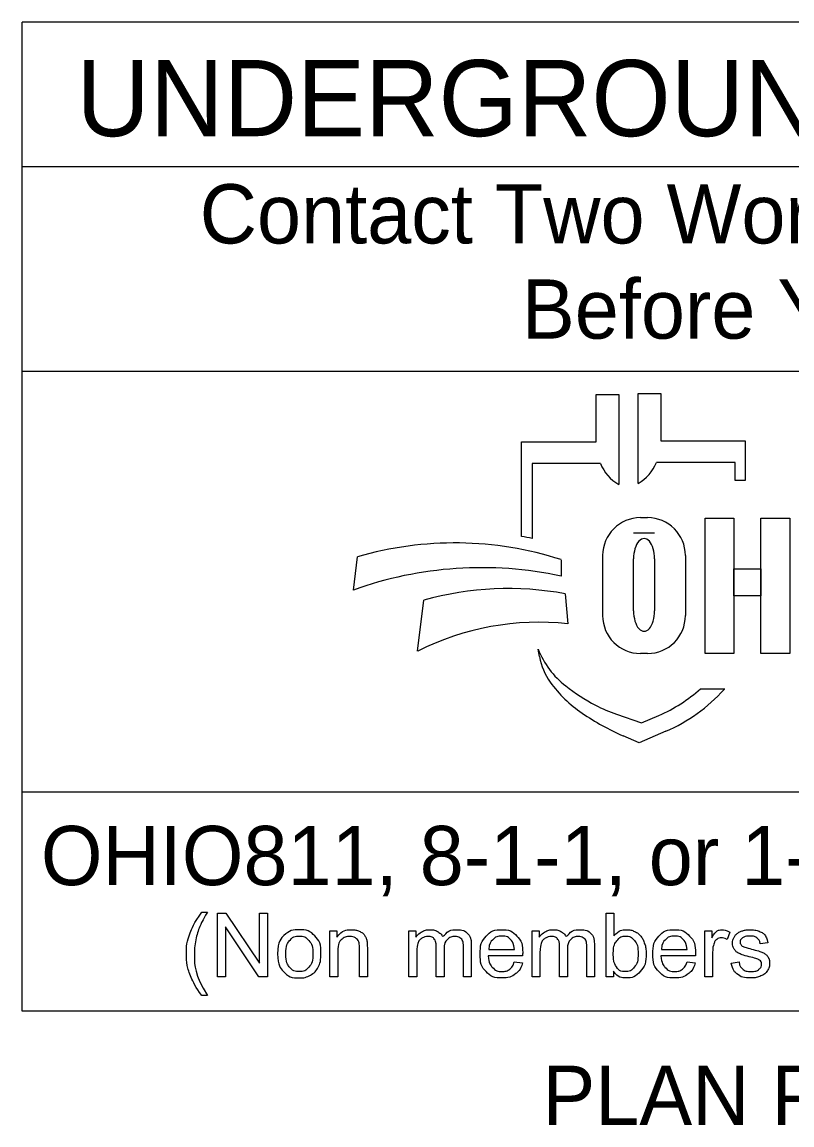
# Model space of a CAD drawing. Extents: x 0 to 34, y 0 to 22.
# Drawn here: x 2.383 to 4.202, y 2.813 to 5.419 of the extents above; entities that cross this region are included whole.
import ezdxf

# ---------------------------------------------------------------- set-up
doc = ezdxf.new("R2010")
doc.units = 0
doc.layers.add('SH_Data', color=7, linetype='Continuous')
doc.layers.add('SH_Text', color=7, linetype='Continuous')

msp = doc.modelspace()

# ---------------------------------------------------------------- linework, layer by layer
at = {"layer": 'SH_Data'}
for p, q in [((2.3833, 3.0815), (2.3833, 5.419)), ((6.6333, 5.419), (2.3833, 5.419)), ((2.3833, 5.0774), (6.6333, 5.0774)), ((2.3833, 4.594), (6.6333, 4.594)), ((6.6333, 3.5994), (2.3833, 3.5994)), ((6.6333, 3.0815), (2.3833, 3.0815))]:
    msp.add_line(p, q, dxfattribs=at)
at = {"layer": 'SH_Text'}
for p, q in [((3.7393, 4.427), (3.7393, 4.5385)), ((3.7393, 4.5385), (3.793, 4.5385)), ((3.793, 4.5385), (3.793, 4.3264)), ((3.8387, 4.3287), (3.8387, 4.5408)), ((3.8387, 4.5408), (3.8923, 4.5408)), ((3.8923, 4.5408), (3.8923, 4.4293)), ((3.5634, 4.2031), (3.5634, 4.427)), ((3.5634, 4.427), (3.7393, 4.427)), ((3.8923, 4.4293), (4.0915, 4.4293)), ((4.0915, 4.4293), (4.0915, 4.3355)), ((3.5886, 4.3755), (3.5886, 4.1987)), ((3.7497, 4.3755), (3.5886, 4.3755)), ((4.0682, 4.3779), (3.8819, 4.3779)), ((4.0682, 4.3355), (4.0682, 4.3779)), ((4.0915, 4.3355), (4.0682, 4.3355)), ((3.8443, 4.2478), (3.8609, 4.2478)), ((3.8776, 4.2108), (3.8278, 4.2108)), ((3.166, 4.0768), (3.1754, 4.1549)), ((3.6567, 4.1484), (3.6567, 4.1096)), ((3.7549, 4.0163), (3.7549, 4.1583)), ((3.8278, 4.0277), (3.8278, 4.1501)), ((3.8776, 4.1501), (3.8776, 4.0277)), ((3.9503, 4.1583), (3.9503, 4.0163)), ((3.6666, 4.0678), (3.6729, 3.9969)), ((3.3178, 3.9323), (3.3325, 4.0524)), ((3.6055, 3.9194), (3.6025, 3.9373)), ((3.8609, 3.9269), (3.8443, 3.9269)), ((3.9858, 3.8435), (4.0432, 3.8435)), ((3.7874, 3.7831), (3.8468, 3.7626)), ((3.8468, 3.7626), (3.8879, 3.7804)), ((3.8408, 3.7156), (3.8034, 3.7321)), ((3.9041, 3.7431), (3.8408, 3.7156))]:
    msp.add_line(p, q, dxfattribs=at)
for points in [[(3.9968, 4.2468), (4.0647, 4.2468), (4.0647, 3.9268), (3.9968, 3.9268)], [(4.1289, 4.2468), (4.1969, 4.2468), (4.1969, 3.9268), (4.1289, 3.9268)], [(4.0647, 4.1269), (4.1289, 4.1269), (4.1289, 4.0629), (4.0647, 4.0629)]]:
    msp.add_lwpolyline(points, close=True, dxfattribs=at)
for points in [[(2.8079, 3.3153), (2.8211, 3.3153)], [(2.8447, 3.1626), (2.8447, 3.3128), (2.865, 3.3128), (2.944, 3.1948), (2.944, 3.3128), (2.963, 3.3128), (2.963, 3.1626), (2.9427, 3.1626), (2.8637, 3.2806), (2.8637, 3.1626), (2.8447, 3.1626)], [(3.7801, 3.1626), (3.7631, 3.1626), (3.7631, 3.3128), (3.7815, 3.3128), (3.7815, 3.2593)], [(3.1106, 3.1626), (3.1106, 3.2715), (3.1272, 3.2715), (3.1272, 3.256)], [(3.297, 3.1626), (3.297, 3.2715), (3.3135, 3.2715), (3.3135, 3.2561)], [(3.5884, 3.1626), (3.5884, 3.2715), (3.6049, 3.2715), (3.6049, 3.2561)], [(3.9962, 3.1626), (3.9962, 3.2715), (4.0128, 3.2715), (4.0128, 3.255)], [(4.0553, 3.268), (4.0488, 3.2509)], [(3.3801, 3.2258), (3.3801, 3.1626), (3.3617, 3.1626), (3.3617, 3.2333)], [(3.4446, 3.2373), (3.4446, 3.1626), (3.4261, 3.1626), (3.4261, 3.2311)], [(3.6715, 3.2258), (3.6715, 3.1626), (3.6531, 3.1626), (3.6531, 3.2333)], [(3.7359, 3.2373), (3.7359, 3.1626), (3.7175, 3.1626), (3.7175, 3.2311)], [(4.1452, 3.2433), (4.1271, 3.2409)], [(3.1291, 3.222), (3.1291, 3.1626), (3.1106, 3.1626)], [(3.199, 3.2295), (3.199, 3.1626), (3.1806, 3.1626), (3.1806, 3.2288)], [(3.3155, 3.219), (3.3155, 3.1626), (3.297, 3.1626)], [(3.5658, 3.2123), (3.4846, 3.2123)], [(3.4857, 3.2274), (3.5464, 3.2274)], [(3.6068, 3.219), (3.6068, 3.1626), (3.5884, 3.1626)], [(3.9738, 3.2123), (3.8926, 3.2123)], [(3.8937, 3.2274), (3.9544, 3.2274)], [(4.0146, 3.2196), (4.0146, 3.1626), (3.9962, 3.1626)], [(3.5462, 3.1978), (3.5653, 3.1954)], [(3.9542, 3.1978), (3.9733, 3.1954)], [(4.0588, 3.1951), (4.077, 3.198)], [(3.7801, 3.1762), (3.7801, 3.1626)], [(2.8211, 3.1184), (2.8079, 3.1184)]]:
    msp.add_lwpolyline(points, dxfattribs=at)
for centre, radius, start, end in [((3.8411, 4.4123), 0.0985, 201.9296, 240.7469), ((3.7905, 4.4146), 0.0985, 299.2531, 338.0704), ((3.8443, 4.1583), 0.0895, 90, 180), ((3.8609, 4.1583), 0.0895, 0, 90), ((3.4353, 3.3941), 0.8191, 79.2074, 81.0007), ((3.4055, 3.3689), 0.8191, 72.1402, 106.3144), ((3.4686, 3.2377), 0.8919, 77.8238, 109.8274), ((3.5325, 3.3481), 0.7322, 79.44, 105.8467), ((3.8443, 4.0163), 0.0895, 180, 270), ((3.8609, 4.0163), 0.0895, 270, 0), ((3.6045, 3.3649), 0.6357, 83.8248, 116.8021), ((3.7899, 4.0094), 0.2008, 201.0457, 232.5314), ((3.7468, 3.9435), 0.1433, 189.6817, 216.0884), ((3.8805, 4.0409), 0.3088, 216.0884, 235.7167), ((3.9824, 4.2606), 0.5173, 232.5314, 241.794), ((3.7445, 4.1109), 0.3602, 293.4582, 312.0712), ((3.7445, 4.1109), 0.401, 293.4582, 317.8286), ((4.047, 4.2852), 0.6044, 235.7167, 246.2325), ((3.8972, 4.1018), 0.3371, 241.794, 250.9821)]:
    msp.add_arc(centre, radius, start, end, dxfattribs=at)
for centre, start_param, end_param in [((3.8527, 4.1501), 4.712389, 7.853982), ((3.8527, 4.0277), 1.570796, 4.712389)]:
    msp.add_ellipse(centre, major_axis=(0, 0.0484), ratio=0.514403, start_param=start_param, end_param=end_param, dxfattribs=at)
for points in [[(2.8079, 3.1184), (2.7927, 3.1377), (2.7821, 3.1635), (2.7715, 3.1893), (2.7715, 3.217), (2.7715, 3.2413), (2.7794, 3.2637), (2.7887, 3.2896), (2.8079, 3.3153)], [(2.8211, 3.3153), (2.8087, 3.294), (2.8047, 3.2849), (2.7985, 3.2707), (2.7949, 3.2554), (2.7905, 3.2362), (2.7905, 3.2169), (2.7905, 3.1676), (2.8211, 3.1184)], [(2.9871, 3.217), (2.9871, 3.2472), (3.0039, 3.2618), (3.018, 3.2739), (3.0381, 3.2739), (3.0605, 3.2739), (3.0748, 3.2592), (3.089, 3.2445), (3.089, 3.2186), (3.089, 3.1976), (3.0827, 3.1856), (3.0764, 3.1735), (3.0644, 3.1669), (3.0524, 3.1602), (3.0381, 3.1602), (3.0153, 3.1602), (3.0012, 3.1749), (2.9871, 3.1895), (2.9871, 3.217)], [(3.0061, 3.217), (3.0061, 3.1961), (3.0152, 3.1857), (3.0243, 3.1753), (3.0381, 3.1753), (3.0518, 3.1753), (3.0609, 3.1858), (3.07, 3.1962), (3.07, 3.2176), (3.07, 3.2378), (3.0609, 3.2482), (3.0517, 3.2586), (3.0381, 3.2586), (3.0243, 3.2586), (3.0152, 3.2483), (3.0061, 3.2379), (3.0061, 3.217)], [(3.1272, 3.256), (3.1392, 3.2739), (3.1618, 3.2739), (3.1717, 3.2739), (3.1799, 3.2703), (3.1881, 3.2668), (3.1922, 3.2611), (3.1963, 3.2553), (3.198, 3.2474), (3.199, 3.2423), (3.199, 3.2295)], [(3.3135, 3.2561), (3.3186, 3.2641), (3.3272, 3.269), (3.3357, 3.2739), (3.3465, 3.2739), (3.3586, 3.2739), (3.3663, 3.2688), (3.3741, 3.2638), (3.3773, 3.2548), (3.3902, 3.2739), (3.4109, 3.2739), (3.4271, 3.2739), (3.4358, 3.2649), (3.4446, 3.2559), (3.4446, 3.2373)], [(3.5653, 3.1954), (3.5608, 3.1787), (3.5486, 3.1694), (3.5364, 3.1602), (3.5175, 3.1602), (3.4936, 3.1602), (3.4796, 3.1749), (3.4656, 3.1896), (3.4656, 3.2161), (3.4656, 3.2436), (3.4798, 3.2587), (3.4939, 3.2739), (3.5164, 3.2739), (3.5382, 3.2739), (3.5521, 3.259), (3.5659, 3.2442), (3.5659, 3.2172), (3.5659, 3.2156), (3.5658, 3.2123)], [(3.5464, 3.2274), (3.5452, 3.2412), (3.5395, 3.2481), (3.5307, 3.2588), (3.5166, 3.2588), (3.5039, 3.2588), (3.4952, 3.2502), (3.4866, 3.2417), (3.4857, 3.2274)], [(3.6049, 3.2561), (3.61, 3.2641), (3.6185, 3.269), (3.627, 3.2739), (3.6379, 3.2739), (3.65, 3.2739), (3.6577, 3.2688), (3.6655, 3.2638), (3.6686, 3.2548), (3.6816, 3.2739), (3.7023, 3.2739), (3.7185, 3.2739), (3.7272, 3.2649), (3.7359, 3.2559), (3.7359, 3.2373)], [(3.7799, 3.2179), (3.7799, 3.1983), (3.7852, 3.1896), (3.7939, 3.1753), (3.8087, 3.1753), (3.8208, 3.1753), (3.8296, 3.1858), (3.8384, 3.1963), (3.8384, 3.2171), (3.8384, 3.2385), (3.8299, 3.2486), (3.8215, 3.2588), (3.8095, 3.2588), (3.7975, 3.2588), (3.7887, 3.2482), (3.7799, 3.2377), (3.7799, 3.2179)], [(3.7815, 3.2593), (3.7932, 3.2739), (3.8113, 3.2739), (3.8213, 3.2739), (3.8303, 3.2698), (3.8393, 3.2658), (3.845, 3.2585), (3.8508, 3.2511), (3.8541, 3.2408), (3.8574, 3.2304), (3.8574, 3.2187), (3.8574, 3.1907), (3.8435, 3.1755), (3.8297, 3.1602), (3.8104, 3.1602), (3.7911, 3.1602), (3.7801, 3.1762)], [(3.9733, 3.1954), (3.9688, 3.1787), (3.9566, 3.1694), (3.9444, 3.1602), (3.9254, 3.1602), (3.9016, 3.1602), (3.8876, 3.1749), (3.8736, 3.1896), (3.8736, 3.2161), (3.8736, 3.2436), (3.8878, 3.2587), (3.9019, 3.2739), (3.9244, 3.2739), (3.9462, 3.2739), (3.9601, 3.259), (3.9739, 3.2442), (3.9739, 3.2172), (3.9739, 3.2156), (3.9738, 3.2123)], [(3.9544, 3.2274), (3.9532, 3.2412), (3.9475, 3.2481), (3.9386, 3.2588), (3.9246, 3.2588), (3.9119, 3.2588), (3.9032, 3.2502), (3.8946, 3.2417), (3.8937, 3.2274)], [(4.0128, 3.255), (4.0191, 3.2665), (4.0245, 3.2702), (4.0299, 3.2739), (4.0363, 3.2739), (4.0456, 3.2739), (4.0553, 3.268)], [(4.1271, 3.2409), (4.1259, 3.2493), (4.12, 3.254), (4.1141, 3.2588), (4.1033, 3.2588), (4.0906, 3.2588), (4.0852, 3.2545), (4.0797, 3.2503), (4.0797, 3.2447), (4.0797, 3.2411), (4.082, 3.2382), (4.0843, 3.2353), (4.0891, 3.2333), (4.0918, 3.2323), (4.1054, 3.2286), (4.125, 3.2234), (4.1327, 3.22), (4.1405, 3.2167), (4.1449, 3.2104), (4.1493, 3.204), (4.1493, 3.1946), (4.1493, 3.1854), (4.1439, 3.1773), (4.1385, 3.1691), (4.1284, 3.1647), (4.1182, 3.1602), (4.1054, 3.1602), (4.0841, 3.1602), (4.073, 3.169), (4.0619, 3.1778), (4.0588, 3.1951)], [(4.077, 3.198), (4.0785, 3.187), (4.0856, 3.1812), (4.0926, 3.1753), (4.1053, 3.1753), (4.118, 3.1753), (4.1242, 3.1805), (4.1303, 3.1857), (4.1303, 3.1927), (4.1303, 3.1989), (4.1249, 3.2025), (4.1211, 3.205), (4.106, 3.2088), (4.0857, 3.2139), (4.0778, 3.2176), (4.07, 3.2214), (4.0659, 3.228), (4.0619, 3.2346), (4.0619, 3.2425), (4.0619, 3.2498), (4.0652, 3.256), (4.0686, 3.2622), (4.0743, 3.2663), (4.0786, 3.2695), (4.0861, 3.2717), (4.0935, 3.2739), (4.102, 3.2739), (4.1148, 3.2739), (4.1245, 3.2702), (4.1342, 3.2665), (4.1388, 3.2602), (4.1435, 3.2539), (4.1452, 3.2433)], [(3.1806, 3.2288), (3.1806, 3.24), (3.1784, 3.2456), (3.1763, 3.2512), (3.1708, 3.2545), (3.1653, 3.2578), (3.1579, 3.2578), (3.1462, 3.2578), (3.1376, 3.2504), (3.1291, 3.2429), (3.1291, 3.222)], [(3.3617, 3.2333), (3.3617, 3.2456), (3.3572, 3.2517), (3.3527, 3.2578), (3.3424, 3.2578), (3.3346, 3.2578), (3.328, 3.2537), (3.3214, 3.2496), (3.3184, 3.2418), (3.3155, 3.2339), (3.3155, 3.219)], [(3.4261, 3.2311), (3.4261, 3.2422), (3.4243, 3.247), (3.4225, 3.2519), (3.4178, 3.2549), (3.4131, 3.2578), (3.4068, 3.2578), (3.3953, 3.2578), (3.3877, 3.2502), (3.3801, 3.2426), (3.3801, 3.2258)], [(3.6531, 3.2333), (3.6531, 3.2456), (3.6486, 3.2517), (3.6441, 3.2578), (3.6338, 3.2578), (3.626, 3.2578), (3.6194, 3.2537), (3.6128, 3.2496), (3.6098, 3.2418), (3.6068, 3.2339), (3.6068, 3.219)], [(3.7175, 3.2311), (3.7175, 3.2422), (3.7157, 3.247), (3.7139, 3.2519), (3.7092, 3.2549), (3.7045, 3.2578), (3.6981, 3.2578), (3.6867, 3.2578), (3.6791, 3.2502), (3.6715, 3.2426), (3.6715, 3.2258)], [(4.0488, 3.2509), (4.0421, 3.2549), (4.0353, 3.2549), (4.0293, 3.2549), (4.0245, 3.2512), (4.0197, 3.2476), (4.0177, 3.2411), (4.0146, 3.2313), (4.0146, 3.2196)], [(3.4846, 3.2123), (3.4857, 3.1944), (3.4948, 3.1848), (3.5039, 3.1753), (3.5175, 3.1753), (3.5277, 3.1753), (3.5349, 3.1807), (3.542, 3.186), (3.5462, 3.1978)], [(3.8926, 3.2123), (3.8937, 3.1944), (3.9028, 3.1848), (3.9119, 3.1753), (3.9255, 3.1753), (3.9357, 3.1753), (3.9428, 3.1807), (3.95, 3.186), (3.9542, 3.1978)]]:
    msp.add_open_spline(points, degree=3, dxfattribs=at)

# ---------------------------------------------------------------- texts
for s, height, p in [('UNDERGROUND UTILITIES', 0.18, (2.5115, 5.1493)), ('Contact Two Working Days', 0.14, (2.803, 4.8958)), ('Before You Dig', 0.14, (3.5641, 4.6708)), ('OHIO811, 8-1-1, or 1-800-362-2764', 0.14, (2.4278, 3.3793)), ('PLAN PREPARED BY:', 0.14, (3.6125, 2.8126))]:
    msp.add_text(s, height=height, dxfattribs=at).set_placement(p)

doc.saveas('drawing.dxf')
